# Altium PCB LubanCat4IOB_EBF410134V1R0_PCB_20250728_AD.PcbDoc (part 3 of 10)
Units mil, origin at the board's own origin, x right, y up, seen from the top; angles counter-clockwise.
Board outline 5236.21 x 4055.11 mil, 6 copper layers (TOP, GND02, ART03, PWR04, GND05, BOTTOM), stack 47.2 mil thick; 614 components, 490 nets, 2311 pads, 1916 vias.
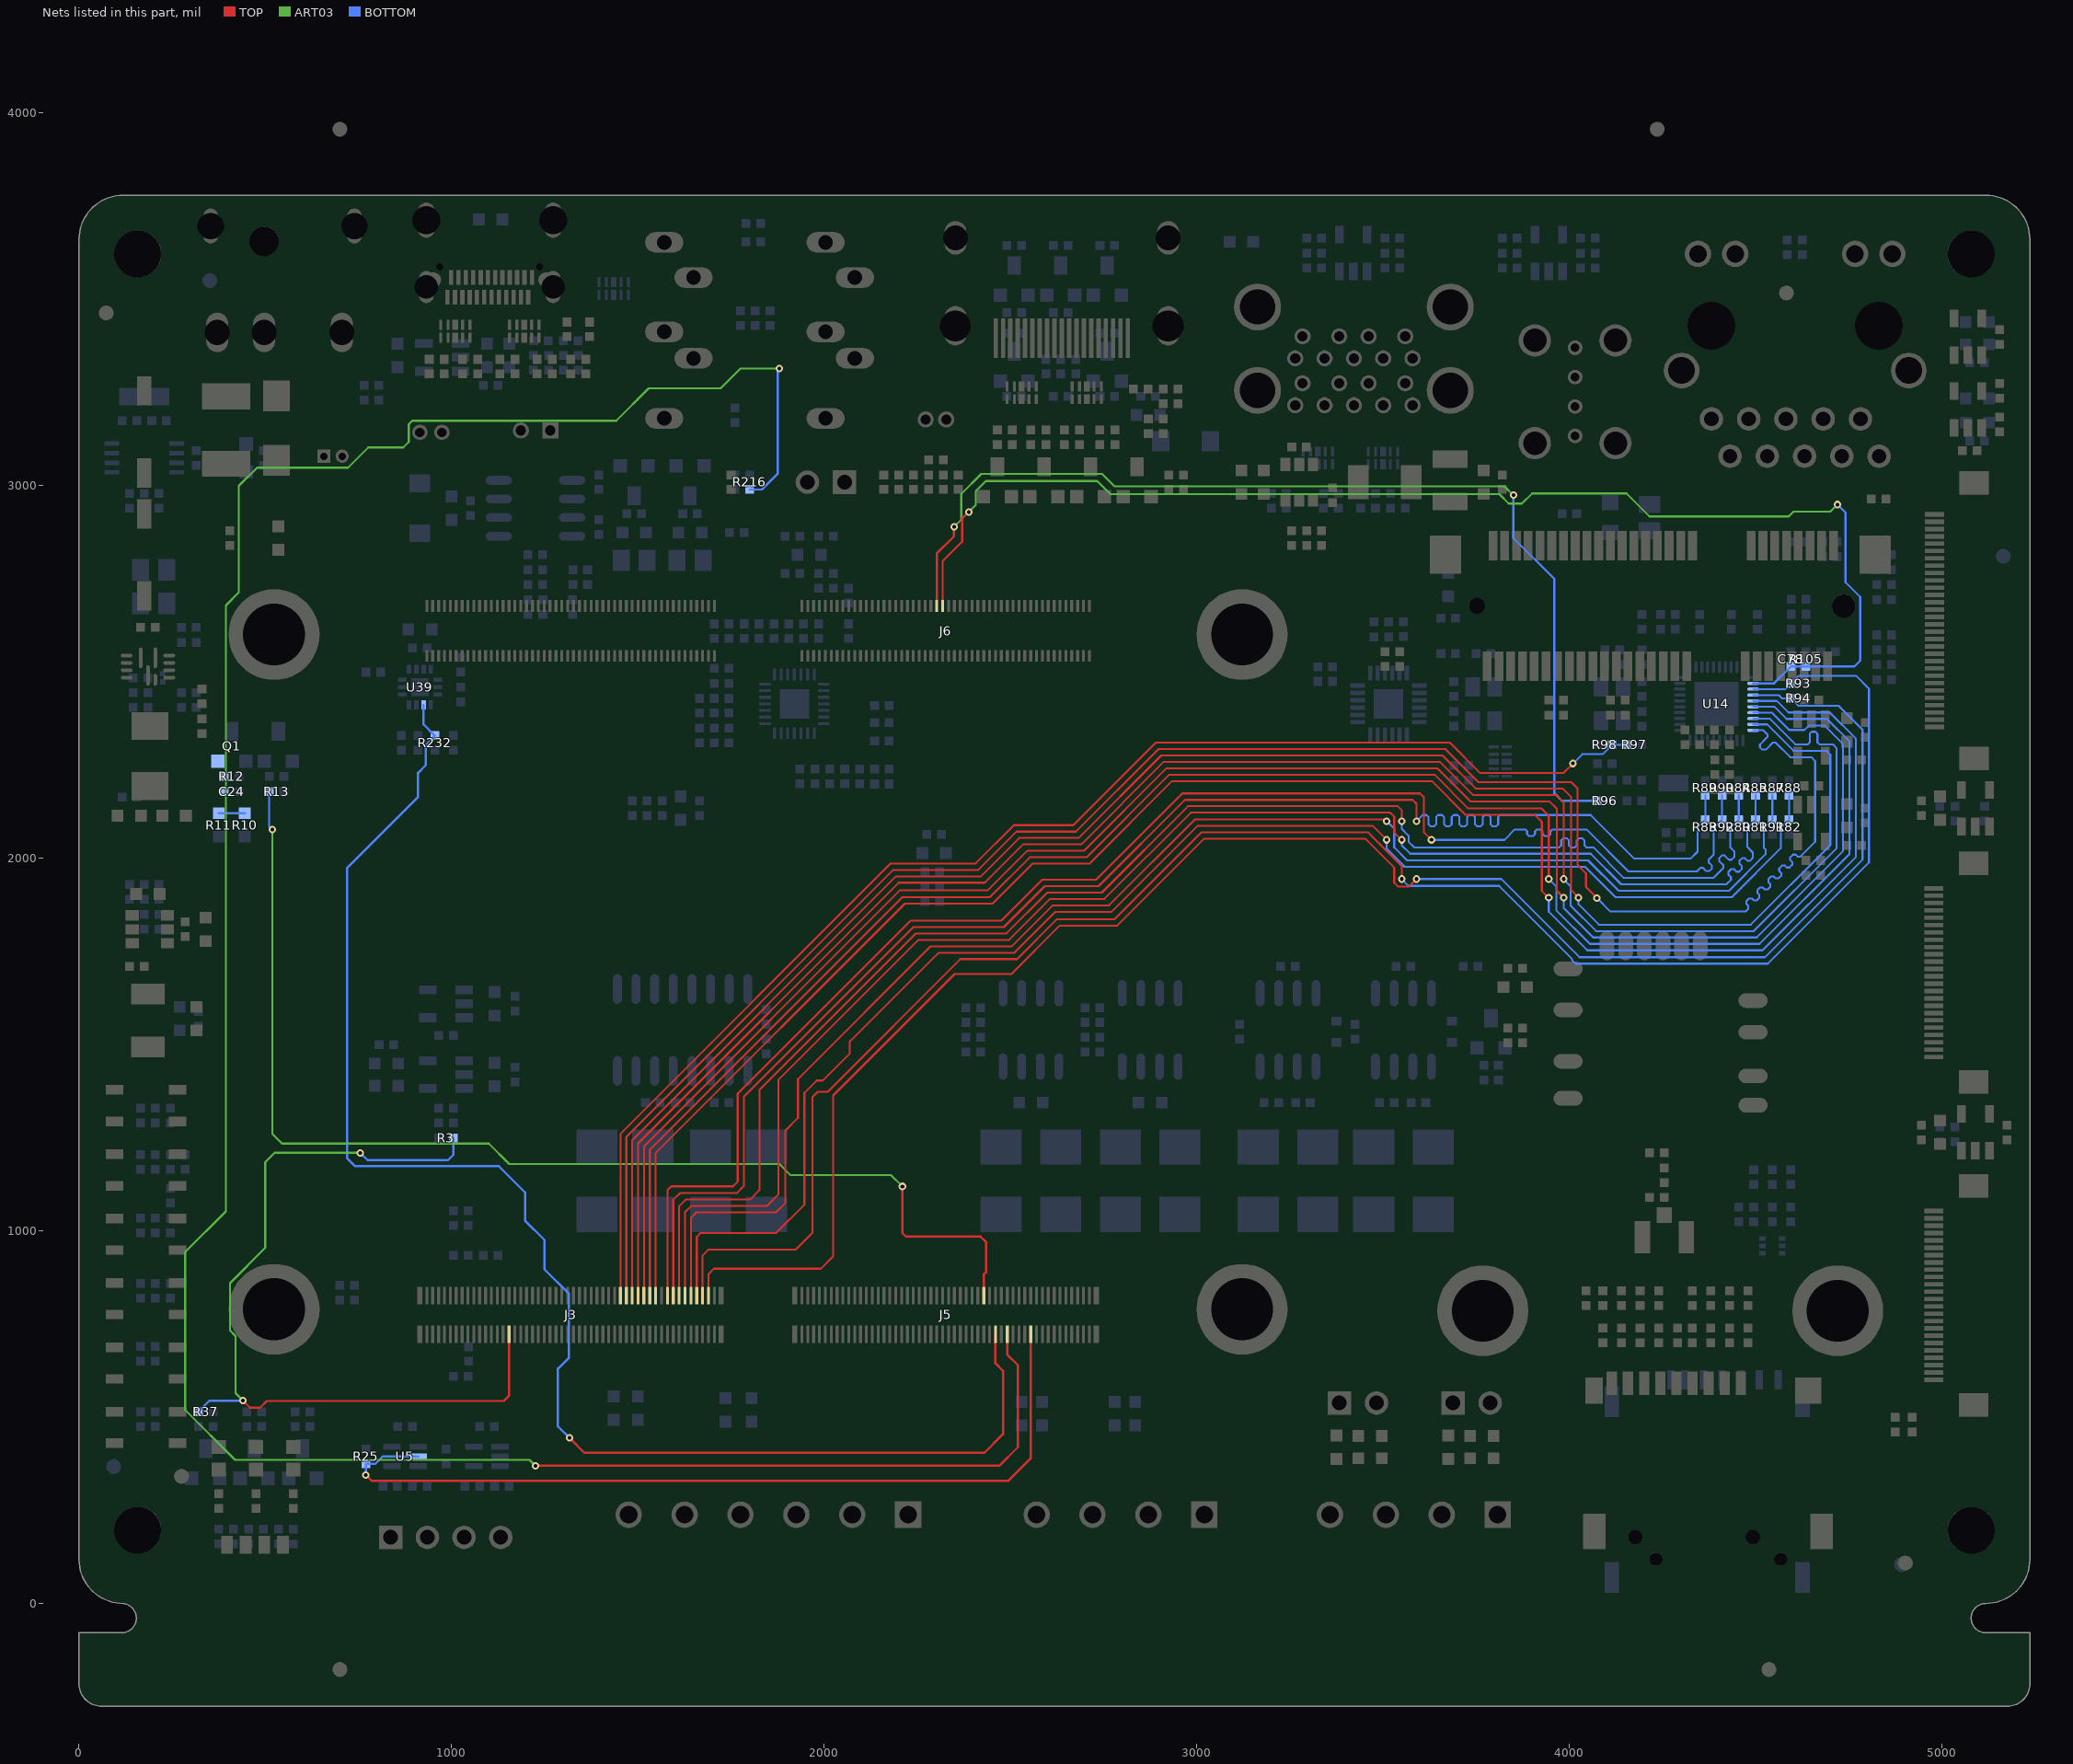
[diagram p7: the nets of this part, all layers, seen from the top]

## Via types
v1: diameter 20, hole 10, TOP to BOTTOM, 1912 vias
v2: diameter 40/50/50/50/50/40 (per signal layer), hole 0, TOP to BOTTOM, 4 vias

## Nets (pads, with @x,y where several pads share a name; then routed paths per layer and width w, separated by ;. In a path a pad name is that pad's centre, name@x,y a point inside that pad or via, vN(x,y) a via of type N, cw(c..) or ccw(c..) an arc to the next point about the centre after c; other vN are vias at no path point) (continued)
DEBUG_TX: J5.80 R25.2 U5.2 | length 2327.7
  TOP w6: v1(770,344.37) 785,329.37 2495,329.37 2554.33,388.7 J5.80@2554.33,722.26
  BOTTOM w6: v1(770,344.37) R25.2@770,374.69 795.32,374.69 815.32,394.69 U5.2@910.43,394.69
EARPHONE_CTL: J5.72 R216.1 | length 7158.8
  TOP w6: v1(1225,369.37) 2470,369.37 2520,419.37 2520,639.37 2491.34,668.03 J5.72@2491.34,722.26
  ART03 w5.5: v1(1225,369.37) 1209,385.37 419,385.37 285,519.37 285,943.37 394,1052.37 394,2678.37 429,2713.37 429,2999.37 478,3048.37 722,3048.37 776,3102.37 870,3102.37 885,3117.37 885,3165 894.37,3174.37 1442,3174.37 1529,3261.37 1722,3261.37 1775,3314.37 v1(1880,3314.37)
  BOTTOM w6: R216.1@1800,2989.69 1833,2989.69 1875,3031.69 1875,3309.37 v1(1880,3314.37)
EXT_PWR_EN: J3.30 R3.1 R37.1 | length 2300.7
  TOP w6: v1(440,544.37) 459,525.37 486,525.37 504,543.37 1140,543.37 1154.03,557.4 J3.30@1154.03,722.26
  ART03 w5.5: v1(440,544.37) 420,564.37 420,717.75 405,732.75 405,859.37 500,954.37 500,1184.37 525,1209.37 v1(755,1209.37)
  BOTTOM w6: R37.1@320.32,514.37 350.32,544.37 v1(440,544.37) ; v1(755,1209.37) 775,1189.37 990,1189.37 1004.68,1204.05 R3.1@1004.68,1249.37
FAN: C24.1 Q1.2 R10.2 R11.2 R12.1 | length 70
  BOTTOM w6: R11.2@375,2120.87 R10.2@445,2120.87
FAN_PWM: J5.63 R13.1 | length 3177.9
  TOP w6: v1(2210,1119.37) 2210,994.37 2220,984.37 2420,984.37 2435,969.37 2435,889.37 2428.34,882.71 J5.63@2428.34,826.59
  ART03 w5.5: v1(519,2077.37) 519,1260.37 545,1234.37 1100,1234.37 1155,1179.37 1880,1179.37 1910,1149.37 2180,1149.37 v1(2210,1119.37)
  BOTTOM w6: R13.1@510.32,2179.37 510.32,2086.05 v1(519,2077.37)
FUSB302_INT: J5.68 R232.2 U39.5 | length 4051.9
  TOP w6: v1(1316.26,444.37) 1356.26,404.37 2430,404.37 2480,454.37 2480,624.37 2459.84,644.53 J5.68@2459.84,722.26
  BOTTOM w6: U39.5@924.84,2411.73 924.84,2359.21 R232.2@955,2329.05 930.8,2304.85 930.8,2250.17 910,2229.37 910,2164.37 720,1974.37 720,1194.37 741,1173.37 1127,1173.37 1197,1103.37 1197,1027.37 1249.18,975.19 1249.18,896.82 1315,831 1315,659.37 1285.62,629.99 1285.62,475.01 v1(1316.26,444.37)
GMAC1_INT: J6.48 R96.1 | length 2824.3
  TOP w6: J6.48@2302.36,2677.37 2302.36,2818.16 2348.57,2864.37 v1(2348.57,2889.37)
  ART03 w5.5: v1(2348.57,2889.37) 2368.25,2909.05 2368.25,2977.62 2422,3031.37 2746,3031.37 2779,2998.37 3826,2998.37 v1(3850,2974.37)
  BOTTOM w6: v1(3850,2974.37) 3850,2859.37 3960,2749.37 3960,2174.37 3980,2154.37 R96.1@4075.32,2154.37
GMAC1_MCLK_INOUT: J3.67 R97.1 R98.1 | length 3635.6
  TOP w5.2: J3.67@1453.24,826.59 1453.24,1260.64 2178.57,1985.97 2406.65,1985.97 2509.45,2088.77 2668.78,2088.77 2890.38,2310.37 3679,2310.37 3760,2229.37 3985,2229.37 v1(4010,2254.37)
  BOTTOM w5.2: v1(4010,2254.37) 4035,2279.37 4089.68,2279.37 R98.1@4114.68,2304.37 R97.1@4155.32,2304.37
GMAC1_MDC: J3.95 R93.2 U14.13 | length 5009.6
  TOP w5.2: J3.95@1673.71,826.59 1673.71,934.08 1689,949.37 1923,949.37 1969,995.37 1969,1359.68 1982.29,1372.97 2009.28,1372.97 2365.68,1729.37 2517.96,1729.37 2625.16,1836.57 2779.88,1836.57 3013.28,2069.97 3459.41,2069.97 3469.47,2059.9 3550,1979.37 v1(3550,1944.37)
  BOTTOM w5.2: v1(3550,1944.37) 3568.6,1925.77 3811.8,1925.77 4007.12,1730.44 4007.12,1727.24 4017.2,1717.17 4532.8,1717.17 4804.4,1988.77 4804.4,2454.97 4769.6,2489.77 4615.72,2489.77 R93.2@4595.32,2469.37 4579.69,2453.74 U14.13@4493.43,2453.74
GMAC1_MDIO: J3.97 R94.2 U14.14 | length 4853.9
  TOP w5.2: J3.97@1689.46,826.59 1689.46,883.83 1704,898.37 1991,898.37 2024,931.37 2024,1363.37 2350,1689.37 2502.28,1689.37 2632.28,1819.37 2787,1819.37 3020.4,2052.77 3452.28,2052.77 3530,1975.05 3530,1934.37 3540,1924.37 3570,1924.37 v1(3590,1944.37)
  BOTTOM w5.2: v1(3590,1944.37) 3817.53,1944.37 4027.53,1734.37 4525,1734.37 4787.2,1996.57 4787.2,2345.17 4723.4,2408.97 4615.72,2408.97 R94.2@4595.32,2429.37 4570.32,2429.37 4561.7,2437.99 U14.14@4493.43,2437.99
GMAC1_RSTN: C78.1 J6.50 R105.2 U14.12 | length 3501.3
  TOP w6: J6.50@2318.1,2677.37 2318.1,2797.47 2370,2849.37 2370,2911.43 v1(2387.94,2929.37)
  ART03 w5.5: v1(2387.94,2929.37) 2407,2948.43 2407,2985.37 2434,3012.37 2733,3012.37 2768,2977.37 3812,2977.37 3837.5,2951.87 3872.9,2951.87 3900.2,2979.17 4153.4,2979.17 4215.2,2917.37 4589,2917.37 4602.25,2930.62 4701.25,2930.62 v1(4720,2949.37)
  BOTTOM w6: U14.12@4493.43,2469.49 4549.8,2469.49 C78.1@4595,2514.69 R105.2@4635,2514.69 4765.32,2514.69 4781,2530.37 4781,2701.37 4741.48,2740.89 4741.48,2927.89 v1(4720,2949.37)
GMAC1_RXCLK: J3.85 R83.1 R89.1 | length 4104.7
  TOP w5.2: J3.85@1594.97,826.59 1594.97,1083.37 1612.97,1101.37 1765,1101.37 1785,1121.37 1785,1361.02 2239.35,1815.37 2482.33,1815.37 2592.13,1925.17 2736.8,1925.17 2968.4,2156.77 3579.6,2156.77 3590,2146.37 v1(3590,2099.37)
  BOTTOM w5.2: v1(3590,2099.37) 3606.6,2115.97 3616.8,2115.97 3622,2110.77 3622,2091.17 3627.2,2085.97 3637.6,2085.97 3642.8,2091.17 3642.8,2110.77 3648,2115.97 3658.4,2115.97 3663.6,2110.77 3663.6,2091.17 3668.8,2085.97 3679.2,2085.97 3684.4,2091.17 3684.4,2110.77 3689.6,2115.97 3700,2115.97 3705.2,2110.77 3705.2,2091.17 3710.4,2085.97 3720.8,2085.97 3726,2091.17 3726,2110.77 3731.2,2115.97 3741.6,2115.97 3746.8,2110.77 3746.8,2091.17 3752,2085.97 3762.4,2085.97 3767.6,2091.17 3767.6,2110.77 3772.8,2115.97 3783.2,2115.97 3788.4,2110.77 3788.4,2091.17 3793.6,2085.97 3804,2085.97 3809.2,2091.17 3809.2,2110.77 3814.4,2115.97 4057.4,2115.97 4173.8,1999.57 4326.2,1999.57 4344.4,2017.77 4344.4,2083.45 R83.1@4365,2104.05 R89.1@4365,2169.69
GMAC1_RXD0: J3.87 R80.2 R84.1 | length 4107.8
  TOP w5.2: J3.87@1610.72,826.59 1610.72,1066.37 1628.32,1083.97 1801,1083.97 1826.4,1109.37 1826.4,1378.1 2246.47,1798.17 2489.46,1798.17 2599.26,1907.97 2745.28,1907.97 2976.88,2139.57 3539.6,2139.57 3550,2129.17 v1(3550,2099.37)
  BOTTOM w5.2: v1(3550,2099.37) 3550,2079.37 3568.6,2060.77 3568.6,2044.46 3583.69,2029.37 3973.09,2029.37 3978.29,2034.57 3978.29,2048.17 3983.49,2053.37 3993.89,2053.37 3999.09,2048.17 3999.09,2034.57 4004.29,2029.37 4014.69,2029.37 4019.89,2034.57 4019.89,2048.17 4025.09,2053.37 4035.49,2053.37 4040.69,2048.17 4040.69,2034.57 4045.89,2029.37 4064.33,2029.37 4146.53,1947.17 4386.48,1947.17 4413.49,1974.18 4413.49,1981.54 4402.17,1992.86 4402.17,2000.21 4409.52,2007.57 4416.88,2007.57 4428.2,1996.24 4435.55,1996.24 4442.98,2003.68 4442.98,2018.39 4432.5,2028.87 4432.5,2081.55 R80.2@4455,2104.05 R84.1@4455,2169.69
GMAC1_RXD1: J3.89 R81.2 R85.1 | length 4096.2
  TOP w5.2: J3.89@1626.47,826.59 1626.47,1050.37 1642.87,1066.77 1846.4,1066.77 1877,1097.37 1877,1404.37 2253.6,1780.97 2496.58,1780.97 2606.38,1890.77 2752.4,1890.77 2984,2122.37 3519.6,2122.37 3530,2111.97 3530,2069.37 v1(3550,2049.37)
  BOTTOM w5.2: v1(3550,2049.37) 3550,2035.05 3572.88,2012.17 4057.2,2012.17 4139.4,1929.97 4421.95,1929.97 4433.98,1941.99 4433.98,1949.35 4427.15,1956.17 4427.15,1963.52 4434.51,1970.88 4441.86,1970.88 4448.68,1964.06 4456.04,1964.06 4463.39,1971.41 4463.39,1978.77 4456.57,1985.59 4456.57,1992.94 4463.92,2000.29 4471.28,2000.29 4478.1,1993.47 4485.45,1993.47 4492.67,2000.69 4492.67,2015.4 4478,2030.06 4478,2082.05 R81.2@4500,2104.05 R85.1@4500,2169.69
GMAC1_RXD2: J3.91 R87.1 R91.1 | length 4029.9
  TOP w5.2: J3.91@1642.22,826.59 1642.22,1034.37 1657.42,1049.57 1870.2,1049.57 1896,1075.37 1896,1269.37 1929.8,1303.17 1929.8,1407.48 2286.09,1763.77 2503.71,1763.77 2613.51,1873.57 2764.47,1873.57 2995.28,2104.37 3505,2104.37 v1(3510,2099.37)
  BOTTOM w5.2: v1(3510,2099.37) 3530,2079.37 3530,2029.37 3565,1994.37 4050.68,1994.37 4132.28,1912.77 4429.07,1912.77 4526.98,2010.68 4526.98,2023.25 4522.5,2027.73 4522.5,2081.55 R91.1@4545,2104.05 R87.1@4545,2169.69
GMAC1_RXD3: J3.93 R82.2 R88.1 | length 4018.5
  TOP w5.2: J3.93@1657.96,826.59 1657.96,983.97 1668.37,994.37 1871,994.37 1947,1070.37 1947,1370.37 1980,1403.37 1996,1403.37 2069,1476.37 2069,1508.37 2307.2,1746.57 2510.83,1746.57 2620.63,1856.37 2771.6,1856.37 3002.4,2087.17 3472.2,2087.17 v1(3510,2049.37)
  BOTTOM w5.2: v1(3510,2049.37) 3510,2025.05 3557.88,1977.17 4042.2,1977.17 4123.8,1895.57 4436.2,1895.57 4567.5,2026.87 4567.5,2081.55 R82.2@4590,2104.05 R88.1@4590,2169.69
GMAC1_RXDV_CRS: J3.83 R90.1 R92.1 | length 4104.4
  TOP w5.2: J3.83@1579.22,826.59 1579.22,1108.97 1589.62,1119.37 1755,1119.37 1767.8,1132.17 1767.8,1368.14 2232.22,1832.57 2475.21,1832.57 2585.01,1942.37 2729.68,1942.37 2961.28,2173.97 3599.6,2173.97 3610,2163.57 3610,2069.37 v1(3630,2049.37)
  BOTTOM w5.2: v1(3630,2049.37) 3826,2049.37 3854,2077.37 3881.8,2077.37 3887,2072.17 3887,2064.57 3892.2,2059.37 3902.6,2059.37 3907.8,2064.57 3907.8,2072.17 3913,2077.37 3923.4,2077.37 3928.6,2072.17 3928.6,2064.57 3933.8,2059.37 3944.2,2059.37 3949.4,2064.57 3949.4,2072.17 3954.6,2077.37 4046.22,2077.37 4159.22,1964.37 4342,1964.37 4351.85,1974.22 4359.2,1974.22 4367.69,1965.74 4376.04,1965.74 4382.9,1972.59 4382.9,1979.94 4373.91,1988.93 4373.91,1996.28 4387.5,2009.87 4387.5,2081.55 R92.1@4410,2104.05 R90.1@4410,2169.69
GMAC1_TXCLK: J3.69 U14.20 | length 5047.7
  TOP w5.2: J3.69@1468.99,826.59 1468.99,1252.07 2185.69,1968.77 2413.78,1968.77 2516.57,2071.57 2675.9,2071.57 2897.5,2293.17 3666.88,2293.17 3755.68,2204.37 4005,2204.37 4022.5,2186.87 4022.5,1981.87 4045,1959.37 4045,1922.61 v1(4074.12,1893.49)
  BOTTOM w5.2: v1(4074.12,1893.49) 4110.64,1856.97 4472.82,1856.97 4480.64,1864.79 4480.64,1872.14 4475.33,1877.45 4475.33,1884.81 4482.68,1892.16 4490.04,1892.16 4495.35,1886.85 4502.7,1886.85 4510.05,1894.2 4510.05,1901.56 4504.74,1906.87 4504.74,1914.22 4512.1,1921.58 4519.45,1921.58 4524.76,1916.27 4532.12,1916.27 4539.47,1923.62 4539.47,1930.97 4534.16,1936.28 4534.16,1943.64 4541.52,1950.99 4548.87,1950.99 4554.18,1945.68 4561.53,1945.68 4568.89,1953.04 4568.89,1960.39 4563.58,1965.7 4563.58,1973.05 4570.93,1980.41 4578.28,1980.41 4583.59,1975.1 4590.95,1975.1 4598.3,1982.45 4598.3,1989.81 4592.99,1995.12 4592.99,2002.47 4600.35,2009.82 4607.7,2009.82 4613.01,2004.52 4620.36,2004.52 4660,2044.15 4660,2260.79 4649.6,2271.19 4593.18,2271.19 4553.82,2310.55 4546.46,2310.55 4527.42,2291.51 4518.06,2291.51 4511.71,2297.86 4511.71,2305.22 4531.76,2325.26 4531.76,2332.61 4520.87,2343.5 U14.20@4493.43,2343.5
GMAC1_TXD0: J3.73 U14.18 | length 5061.8
  TOP w5.2: J3.73@1500.48,826.59 1500.48,1234.91 2199.94,1934.37 2431.03,1934.37 2533.82,2037.17 2690.15,2037.17 2911.75,2258.77 3652.62,2258.77 3741.43,2169.97 3964.4,2169.97 3985,2149.37 v1(3985,1944.37)
  BOTTOM w5.2: v1(3985,1944.37) 3991.4,1937.97 3991.4,1936.66 4003.6,1924.46 4003.6,1872.77 4071.8,1804.57 4495.2,1804.57 4717.8,2027.17 4717.8,2295.37 4707.4,2305.77 4671.4,2305.77 4666.2,2310.97 4666.2,2334.17 4661,2339.37 4650.6,2339.37 4645.4,2334.17 4645.4,2310.97 4640.2,2305.77 4606.6,2305.77 4537.37,2375 U14.18@4493.43,2375
GMAC1_TXD1: J3.75 U14.17 | length 5042.2
  TOP w5.2: J3.75@1516.23,826.59 1516.23,1226.34 2204.27,1914.37 2439.35,1914.37 2544.95,2019.97 2697.28,2019.97 2918.88,2241.57 3645.5,2241.57 3734.3,2152.77 3748.55,2152.77 3946.6,2152.77 3966.4,2132.97 3966.4,1912.97 v1(3985,1894.37)
  BOTTOM w5.2: v1(3985,1894.37) 3985,1866.37 4064,1787.37 4503,1787.37 4735,2019.37 4735,2306.37 4684.8,2356.57 4643.48,2356.57 4631.27,2344.37 4590,2344.37 4543.62,2390.75 U14.17@4493.43,2390.75
GMAC1_TXD2: J3.77 U14.16 | length 5052.6
  TOP w5.2: J3.77@1531.98,826.59 1531.98,1217.76 2209.79,1895.57 2444.88,1895.57 2552.07,2002.77 2704.4,2002.77 2926,2224.37 3638.38,2224.37 3729.18,2133.57 3925.8,2133.57 3945,2114.37 v1(3945,1944.37)
  BOTTOM w5.2: v1(3945,1944.37) 3965,1924.37 3965,1860.69 4055.53,1770.17 4510.8,1770.17 4752.2,2011.57 4752.2,2313.5 4691.53,2374.17 4583.2,2374.17 4550.87,2406.5 U14.16@4493.43,2406.5
GMAC1_TXD3: J3.79 U14.15 | length 5075.8
  TOP w5.2: J3.79@1547.73,826.59 1547.73,1209.18 2216.92,1878.37 2452,1878.37 2559.2,1985.57 2712.2,1985.57 2933.8,2207.17 3631.25,2207.17 3722.05,2116.37 3908,2116.37 3926.4,2097.97 3926.4,1912.02 3944.05,1894.37 v1(3945,1894.37)
  BOTTOM w5.2: v1(3945,1894.37) 3945,1856.37 4048.4,1752.97 4518.6,1752.97 4769.4,2003.77 4769.4,2320.62 4698.65,2391.37 4588,2391.37 4557.13,2422.24 U14.15@4493.43,2422.24
GMAC1_TXEN: J3.71 U14.19 | length 4977.7
  TOP w5.2: J3.71@1484.74,826.59 1484.74,1243.49 2192.82,1951.57 2420.9,1951.57 2523.7,2054.37 2683.03,2054.37 2904.62,2275.97 3659.75,2275.97 3748.55,2187.17 3982.2,2187.17 4005,2164.37 4005,1914.37 v1(4025,1894.37)
  BOTTOM w5.2: v1(4025,1894.37) 4025,1876.37 4079.6,1821.77 4487.4,1821.77 4700.6,2034.97 4700.6,2277.99 4690.2,2288.39 4601.98,2288.39 4531.12,2359.25 U14.19@4493.43,2359.25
